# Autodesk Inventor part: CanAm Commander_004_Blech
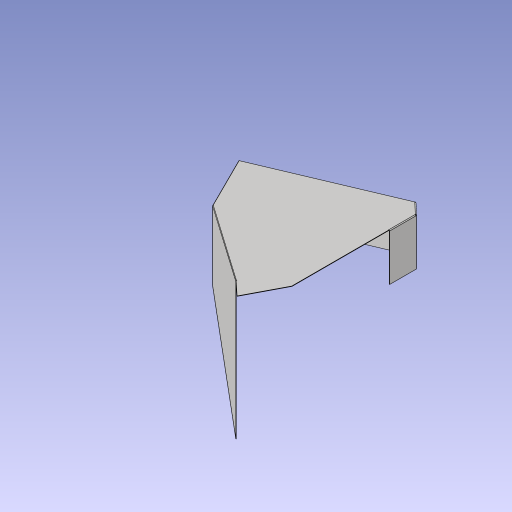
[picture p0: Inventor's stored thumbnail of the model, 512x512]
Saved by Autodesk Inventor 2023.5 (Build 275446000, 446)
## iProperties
Part Number: CanAm Commander_004_Blech
Material: Generisch
Document SubType Name: Blech
Designer: wondraschek
Density: 1 g/cm^3
Sheet Metal Rule: Standard_mm
Appearance: Vorgabe
Flat Pattern Width: 43.3518 cm
Flat Pattern Length: 56.9721 cm
Flat Pattern Area: 2469.84 cm^2
Sheet Metal Width: 433,518 mm
Sheet Metal Length: 569,721 mm
Sheet Metal Area: 246984,386 mm^2
Stärke: 0
Breite: 0
Höhe: 0
Länge: 0
da: 0
di: 0
Author: wondraschek
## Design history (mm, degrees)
derived "CanAm Commander_SKI.ipt"
sketch "Skizze5"
  geometry: L1 (-419.327, 202.793)-(-34.481, 118.507) reference; L2 (-339.291, 91.082)-(-419.327, 202.793) reference; L3 (-100.434, -90.565)-(-339.291, 91.082) reference; L4 (-58.187, -127.395)-(-100.434, -90.565) reference; L5 (0, -98.088)-(-58.187, -127.395) reference; L6 (0, -98.088)-(0, 0) reference; L7 (0, 0)-(0, 47.836) reference; L8 (-34.481, 118.507)-(0, 87.993) reference; L9 (0, 87.993)-(0, 47.836) reference; 1 further point
sketch "Skizze6"
  geometry: L1 (0, 204.965)-(-282.592, 104.02) reference; L2 (-282.592, 0)-(-282.592, 104.02) reference; L3 (0, 0)-(-282.592, 0) reference; L4 (0, 0)-(0, 204.965) reference; 1 further point
sketch "Skizze7"
  geometry: L1 (104.02, 0)-(70.196, 133.195) reference; L2 (0, 133.195)-(70.196, 133.195) reference; L3 (0, 0)-(0, 133.195) reference; L4 (0, 0)-(104.02, 0) reference; 1 further point
sketch "Skizze8"
  geometry: L1 (358.828, -92.447)-(0, 70.196) reference; L2 (0, 70.196)-(0, 0) reference; L3 (0, 0)-(358.828, -162.643) reference; L4 (358.828, -92.447)-(358.828, -162.643) reference; 1 further point
sketch "Skizze9"
  geometry: L1 (43.677, 55.623)-(0, 70.196) reference; L2 (0, 70.196)-(0, 0) reference; L3 (0, 0)-(43.677, -14.572) reference; L4 (43.677, 55.623)-(43.677, -14.572) reference; 1 further point
sketch "Skizze10"
  geometry: L1 (0, 40.157)-(-70.196, 40.157) reference; L2 (0, 0)-(0, 40.157) reference; L3 (0, 0)-(-70.196, 0) reference; L4 (-70.196, 40.157)-(-70.196, 0) reference; 1 further point
node "Fläche4"
node "Fläche5"
node "Fläche6"
node "Fläche7"
node "Fläche8"
node "Fläche9"
node "Volumenkörper4"
tag "Bezeichnung1"
feature "Grobblech4" dims "d34" = 0.5 (= Stärke_1)
feature "Grobblech5" dims "d34" = 0.5 (= Stärke_1), "d35" = 0.5 (= Biegeradius), "d36" = 0.5 (= BreiteBiegungsfreistellung), "d38" = 1 (= MinimalRest)
feature "Biegung7" dims "d34" = 0.5 (= Stärke_1), "d35" = 0.5 (= Biegeradius), "d36" = 0.5 (= BreiteBiegungsfreistellung), "d37" = 0.25 (= TiefeBiegungsfreistellung), "d38" = 1 (= MinimalRest), "d39" = 0.5 (= Übergangsradius), "AbstandVerbindung" = 0.01
feature "Grobblech6" dims "d34" = 0.5 (= Stärke_1), "d40" = 0.5 (= Biegeradius), "d41" = 0.5 (= BreiteBiegungsfreistellung), "d43" = 1 (= MinimalRest)
feature "Biegung8" dims "d34" = 0.5 (= Stärke_1), "d40" = 0.5 (= Biegeradius), "d41" = 0.5 (= BreiteBiegungsfreistellung), "d42" = 0.25 (= TiefeBiegungsfreistellung), "d43" = 1 (= MinimalRest), "d44" = 0.5 (= Übergangsradius), "AbstandVerbindung" = 0.01
feature "Grobblech7" dims "d34" = 0.5 (= Stärke_1), "d45" = 0.5 (= Biegeradius), "d46" = 0.5 (= BreiteBiegungsfreistellung), "d48" = 1 (= MinimalRest)
feature "Biegung9" dims "d34" = 0.5 (= Stärke_1), "d45" = 0.5 (= Biegeradius), "d46" = 0.5 (= BreiteBiegungsfreistellung), "d47" = 0.25 (= TiefeBiegungsfreistellung), "d48" = 1 (= MinimalRest), "d49" = 0.5 (= Übergangsradius), "AbstandVerbindung" = 0.01
feature "Grobblech8" dims "d34" = 0.5 (= Stärke_1), "d50" = 0.5 (= Biegeradius), "d51" = 0.5 (= BreiteBiegungsfreistellung), "d53" = 1 (= MinimalRest)
feature "Biegung10" dims "d34" = 0.5 (= Stärke_1), "d50" = 0.5 (= Biegeradius), "d51" = 0.5 (= BreiteBiegungsfreistellung), "d52" = 0.25 (= TiefeBiegungsfreistellung), "d53" = 1 (= MinimalRest), "d54" = 0.5 (= Übergangsradius), "AbstandVerbindung" = 0.01
feature "Grobblech9" dims "d34" = 0.5 (= Stärke_1), "d55" = 0.5 (= Biegeradius), "d56" = 0.5 (= BreiteBiegungsfreistellung), "d58" = 1 (= MinimalRest)
feature "Biegung11" dims "d34" = 0.5 (= Stärke_1), "d55" = 0.5 (= Biegeradius), "d56" = 0.5 (= BreiteBiegungsfreistellung), "d57" = 0.25 (= TiefeBiegungsfreistellung), "d58" = 1 (= MinimalRest), "d59" = 0.5 (= Übergangsradius), "AbstandVerbindung" = 0.01
feature "Volumenkörper1::CanAm Commander_SKI.ipt"
node "Flä1"
feature "Definition1"
other parameters: "Stärke_1" = 0.5 (derived), "KFaktor" = 4.4, "Biegeradius" = 0.5 (= Stärke_1), "BreiteBiegungsfreistellung" = 0.5 (= Stärke_1), "TiefeBiegungsfreistellung" = 0.25 (= 0.5 x Stärke_1), "GrößeEckenfreistellung" = 2 (= 4 x Stärke_1), "MinimalRest" = 1 (= 2 x Stärke_1), "Übergangsradius" = 0.5 (= Biegeradius), "JacobiRadiusGröße" = 0.5 (= Biegeradius), "Abstandsgröße" = 0.5 (= Stärke_1), "Stärke" = 0 [user parameter], "Breite" = 0 [user parameter], "Höhe" = 0 [user parameter], "Länge" = 0 [user parameter], "da" = 0 [user parameter], "di" = 0 [user parameter], "Breite" = 0, "Höhe" = 0, "Länge" = 0, "Stärke" = 0, "da" = 0, "di" = 0, "Abstandsgröße" = 0.5, "Biegeradius" = 0.5, "BreiteBiegungsfreistellung" = 0.5, "GrößeEckenfreistellung" = 2, "JacobiRadiusGröße" = 0.5, "MinimalRest" = 1, "Stärke_1" = 0.5, "TiefeBiegungsfreistellung" = 0.25, "Übergangsradius" = 0.5
